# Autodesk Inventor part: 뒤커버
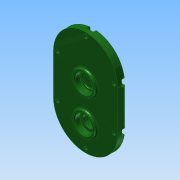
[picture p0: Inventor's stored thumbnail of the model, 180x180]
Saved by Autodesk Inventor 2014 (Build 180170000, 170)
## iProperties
Created: 2016-12
Part Number: 뒤커버
Material: 알루미늄 6061
Document SubType Name: Modeling
Designer: mduedu
Density: 2.71 g/cm^3
Appearance: 매끄러움 - 짙은 산림 녹색
Mass: 235.458 g
Surface Area: 237.575 cm^2
Volume: 86.8849 cm^3
Author: mduedu
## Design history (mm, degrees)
sketch "스케치1"
  geometry: L1 (40, -25)-(40, 25); L2 (-40, 25)-(-40, -25); L3 (-40, -25)-(40, 25); L4 (40, -25)-(-40, 25); A1 r 40 centre (0, 25) between (40, 25) and (-40, 25); A2 r 40 centre (0, -25) between (-40, -25) and (40, -25); 1 further point
  constraints: 8 end point, 4 point on circle, 4 tangent, 2 centre point, 2 midpoint, 1 parallel, 1 vertical
  dimensions: "d0" = 130 dimension on A2 A1; "d2" = 80 distance between parallel lines of L1 L2
extrude "돌출1" new body sketch "스케치1" distance "d3" = 10; taper "d4" = 0 deg
sketch "스케치2"
  geometry: C1 r 14 at (0, 11); 1 further point
  constraints: 1 centre point, 1 vertical alignment
  dimensions: "d5" = 28 diameter of C1; "d6" = 11 distance of C1.centre point (0, 0)
extrude "돌출2" join sketch "스케치2" distance "d7" = 3; taper "d8" = 0 deg
sketch "스케치3"
  geometry: C1 r 14 at (0, -33.1); C2 r 14 at (0, 11) reference; 1 further point
  constraints: 1 centre point, 1 vertical alignment
  dimensions: "d9" = 28 diameter of C1; "d69" = 44.1 distance of C1.centre C2.centre
extrude "돌출3" join sketch "스케치3" distance "d11" = 3; taper "d12" = 0 deg
hole "구멍1" diameter "d15" = 22; stored, may be unused: countersink angle "d19" = 90 deg, drill point angle "d21" = 0 deg; dims "d13" = 10, "d14" = 10, "d16" = 6, "d17" = 4, "d18" = 2, "d20" = 7
hole "구멍2" diameter "d24" = 18; stored, may be unused: countersink angle "d28" = 90 deg, drill point angle "d30" = 0 deg; dims "d22" = 10, "d23" = 10, "d25" = 6, "d26" = 4, "d27" = 2, "d29" = 1
hole "구멍3" diameter "d33" = 22; stored, may be unused: countersink angle "d37" = 90 deg, drill point angle "d39" = 0 deg; dims "d31" = 10, "d32" = 10, "d34" = 6, "d35" = 4, "d36" = 2, "d38" = 7
sketch "스케치4"
  geometry: C1 r 14 at (0, -33.1) reference; C2 r 18 at (0, -33.1); 1 further point
  constraints: 1 centre point, 1 coincident
  dimensions: "d40" = 36 diameter of C2
extrude "돌출4" join sketch "스케치4" distance "d41" = 4; taper "d42" = 0 deg
hole "구멍4" diameter "d45" = 22; stored, may be unused: countersink angle "d49" = 90 deg, drill point angle "d51" = 0 deg; dims "d43" = 10, "d44" = 10, "d46" = 6, "d47" = 4, "d48" = 2, "d50" = 7
hole "구멍5" diameter "d54" = 15; stored, may be unused: countersink angle "d58" = 90 deg, drill point angle "d60" = 0 deg; dims "d52" = 10, "d53" = 10, "d55" = 6, "d56" = 4, "d57" = 2, "d59" = 7
fillet "모깎기1" dims "d61" = 0.3
fillet "모깎기2" dims "d62" = 2
chamfer "모따기1" distance "d63" = 1; stored, may be unused: second distance "d64" = 2, angle "d65" = 45 deg
fillet "모깎기3" dims "d66" = 2
fillet "모깎기4" dims "d67" = 2
fillet "모깎기5" dims "d68" = 2
sketch "스케치5"
  geometry: L1 (-40, 25)-(-40, -25) reference; L2 (40, -25)-(40, 25) reference; L3 (35, 25)-(35, -25); L4 (-35, -25)-(-35, 25); A1 r 40 centre (0, 25) between (40, 25) and (-40, 25) reference; A2 r 40 centre (0, -25) between (-40, -25) and (40, -25) reference; A3 r 35 centre (0, 25) between (35, 25) and (-35, 25); A4 r 35 centre (0, -25) between (-35, -25) and (35, -25); 2 further points
  constraints: 5 point on circle, 4 end point, 2 centre point, 1 vertical alignment, 3 other
  dimensions: "d70" = 5 distance between parallel lines of L2 L3
sketch "스케치6"
  geometry: 1 further point
hole "구멍6" sketch "스케치6" at (0, 60) diameter "d71" = 4.5; stored, may be unused: countersink angle "d75" = 90 deg, drill point angle "d77" = 0 deg; dims "d72" = 6, "d73" = 8, "d74" = 4.6, "d76" = 8
sketch "스케치7"
  geometry: L1 (-4, 0)-(4, 0); L2 (4, 0)-(4, 5); L3 (4, 5)-(-4, 5); L4 (-4, 5)-(-4, 0); C1 r 2.25 at (0, 0) reference; A1 r 40 centre (0, -35) between (40, -35) and (-40, -35) reference; 2 further points
  constraints: 8 end point, 2 parallel, 2 vertical, 1 horizontal, 1 horizontal alignment, 1 perpendicular, 1 tangent, 1 other
extrude "돌출5" cut sketch "스케치7" stored distance "d80" = 10; taper "d81" = 0 deg
fillet "모깎기6" dims "d82" = 0.3
fillet "모깎기7" dims "d83" = 0.3
node "솔리드1"
pattern_linear "직사각형 패턴1"
node "투영된 루프1"
